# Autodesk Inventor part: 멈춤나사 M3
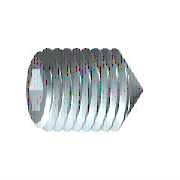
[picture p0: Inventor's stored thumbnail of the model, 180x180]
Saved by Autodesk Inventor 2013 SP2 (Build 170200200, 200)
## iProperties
IsCustomPart: 1
Created: 2012-02
Part Number: 멈춤나사 M3
Material: 강철, 연강
Description: 6각 소켓 머리 없는 멈춤 나사
Document SubType Name: Modeling
Standard: KS B 1028
Designer: test
Standards Organization: KS
Language: ko-KR
Size Designation: 원추점 M3x8
Categories: <MemberInstance><Categories><Category DisplayName="조임쇠" InternalName="e4da775c-781d-43d5-af7c-5136215cf5a6" Mnemonic="FSTN"><Category DisplayName="볼트" InternalN
Density: 1 g/cm^3
Author: test
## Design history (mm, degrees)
sketch "스케치1"
  geometry: L1 (0, 0)-(3.5, 0); L2 (6, 0.866)-(6, 1.5); L3 (6, 1.5)-(0, 1.5); L4 (6, 0.866)-(4, 0.866); L5 (4, 0.866)-(3.5, 0); L6 (0, -0.3)-(0, 1.8) reference; L7 (0, 1.5)-(0, 0)
  constraints: 13 end point, 3 parallel, 1 collinear, 1 perpendicular, 1 point on line
  dimensions: "d0" = 2 distance of L2.start L4.end (= INTI); "d1" = 60 deg angle of L5 L1; "d2" = 3 diameter of L3 L1 (= NND); "d3" = 1.73205 diameter of L4 L1 (= 1.1547 x SW); "d5" = 6 distance from line of L2 L3.end (= NLG)
revolve "본체" sketch "스케치1" stored, may be unused: angle "d6" = 90 deg
sketch "스케치2"
  geometry: L1 (-0.433, 0.75)-(0.433, 0.75); L2 (0.433, 0.75)-(0.866, 0); L3 (0.866, 0)-(0.433, -0.75); L4 (0.433, -0.75)-(-0.433, -0.75); L5 (-0.433, -0.75)-(-0.866, 0); L6 (-0.866, 0)-(-0.433, 0.75); 3 further points
  constraints: 12 end point, 1 coincident, 1 horizontal, 13 other
extrude "슬롯" join sketch "스케치2" taper "d7" = 0 deg; stored distance "d21" = 10
workaxis "Work Axis1"
workplane "Work Plane1"
sketch "스케치4"
  geometry: L1 (0, 0.15)-(-1.35, 1.5) reference; L2 (0, -0.15)-(-1.35, -1.5) reference; L3 (-1.35, -1.5)-(0.15, 0); L4 (-1.35, 1.5)-(0.15, 0); 2 further points
  constraints: 4 end point, 1 coincident, 1 collinear, 1 horizontal alignment
node "작업점1"
body "Solid1"
feature "스레드" dims "d12" = 6 (= NLG), "d13" = 0
chamfer "모따기1" distance "d8" = 1.35 (computed from NND, SPD, FAWI); stored, may be unused: angle "d9" = 45 deg (= FAWI), second distance "d34" = 1.35 (computed from NND, SPD, FAWI)
chamfer "모따기2" distance "d10" = 0.30673 (= -0.5 x GD1 + 0.5 x NND); stored, may be unused: angle "d11" = 45 deg (= FAWI), second distance "d35" = 0.30673 (= -0.5 x GD1 + 0.5 x NND)
other parameters: "NND" = 3 [user parameter; used in 5 equation terms], "NLG" = 6 [user parameter; used in 2 equation terms], "INTI" = 2 [user parameter; used in 1 equation term], "FAWI" = 45 deg [user parameter; used in 4 equation terms], "SW" = 1.5 [user parameter; used in 2 equation terms], "GD1" = 2.38655 (= THREADDIA - 1.2269 x PTC) [user parameter; used in 2 equation terms], "d4" = 0, "FAWI1" = 45 deg [user parameter], "SPD" = 0.3 [user parameter; used in 2 equation terms], "d36" = 0, "d37" = 0, "GUL" = 0.30673 (= 0.61345 x PTC) [user parameter], "TOA" = 30 deg [user parameter], "THREADDIA" = 3 [user parameter; used in 1 equation term], "PTC" = 0.5 [user parameter; used in 4 equation terms], "GAL" = 0.30673 (= 0.61345 x PTC) [user parameter], "E0" = 1.7325 (= 1.155 x SW) [user parameter]
